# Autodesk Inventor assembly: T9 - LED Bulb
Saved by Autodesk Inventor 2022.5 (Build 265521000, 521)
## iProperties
Created: 2024-07
Part Number: T9 - LED Bulb
Document SubType Name: Assembly
Designer: AdminForWorker
Title: T9 - LED Bulb
Author: AdminForWorker
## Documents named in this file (3)
- z:\worker\convert-fusion-r03-cosv3\tmp\job-1\79\temp\files\3a003a07-c448-400c-9cf1-292e8316b43e\T9 - LED Bulb.iam
- z:\worker\convert-fusion-r03-cosv3\tmp\job-1\79\temp\files\3a003a07-c448-400c-9cf1-292e8316b43e\T9.ipt
- z:\worker\convert-fusion-r03-cosv3\tmp\job-1\79\temp\files\3a003a07-c448-400c-9cf1-292e8316b43e\E26 Base.ipt
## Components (2 placed, 2 different names)
1. T9:1
2. E26 Base:1
